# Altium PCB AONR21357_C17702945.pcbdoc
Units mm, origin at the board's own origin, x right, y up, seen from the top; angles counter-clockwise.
Board outline 16.06 x 17.24 mm, 2 copper layers (Top Layer, Bottom Layer), stack 0 mm thick; 1 components, 0 nets, 5 pads, 0 vias.
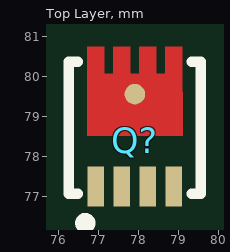
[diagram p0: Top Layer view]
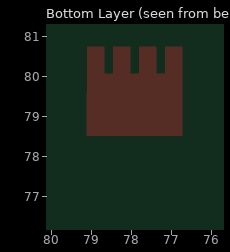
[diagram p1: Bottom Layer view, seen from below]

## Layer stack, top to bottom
Top Layer: signal copper (thickness not stored)
Bottom Layer: signal copper (thickness not stored)

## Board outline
85.91,69.85 69.85,69.85 69.85,87.088 85.91,87.088

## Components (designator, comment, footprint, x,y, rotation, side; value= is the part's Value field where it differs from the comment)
Q? "AONR21357" POWERDI3333-8_DMN7022LFGQ-7 77.91,78.263 r0 top

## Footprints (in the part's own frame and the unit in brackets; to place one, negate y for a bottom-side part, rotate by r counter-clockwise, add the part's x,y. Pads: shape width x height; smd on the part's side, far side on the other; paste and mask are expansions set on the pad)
POWERDI3333-8_DMN7022LFGQ-7 [mm]
  rect 0.42x1 smd paste-100 mask+0.051: 1(-0.975,-1.025) 2(-0.325,-1.025) 3(0.325,-1.025) 4(0.975,-1.025)
  round 0.517 smd: 5(0.003,1.289)
  Top Layer region: -1.19,0.245 -1.19,2.475 -0.76,2.475 -0.76,1.805 -0.54,1.805 -0.54,2.475 -0.11,2.475 -0.11,1.805 0.11,1.805 0.11,2.475 0.54,2.475 0.54,1.805 0.76,1.805 0.76,2.475 1.19,2.475 1.2,0.245
  silkscreen extent -1.65,-2.06 1.65,2.1

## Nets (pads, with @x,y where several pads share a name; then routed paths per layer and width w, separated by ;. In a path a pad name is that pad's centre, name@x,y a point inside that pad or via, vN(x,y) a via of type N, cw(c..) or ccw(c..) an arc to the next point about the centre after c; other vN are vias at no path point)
pads on no net: Q?.1 Q?.2 Q?.3 Q?.4 Q?.5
